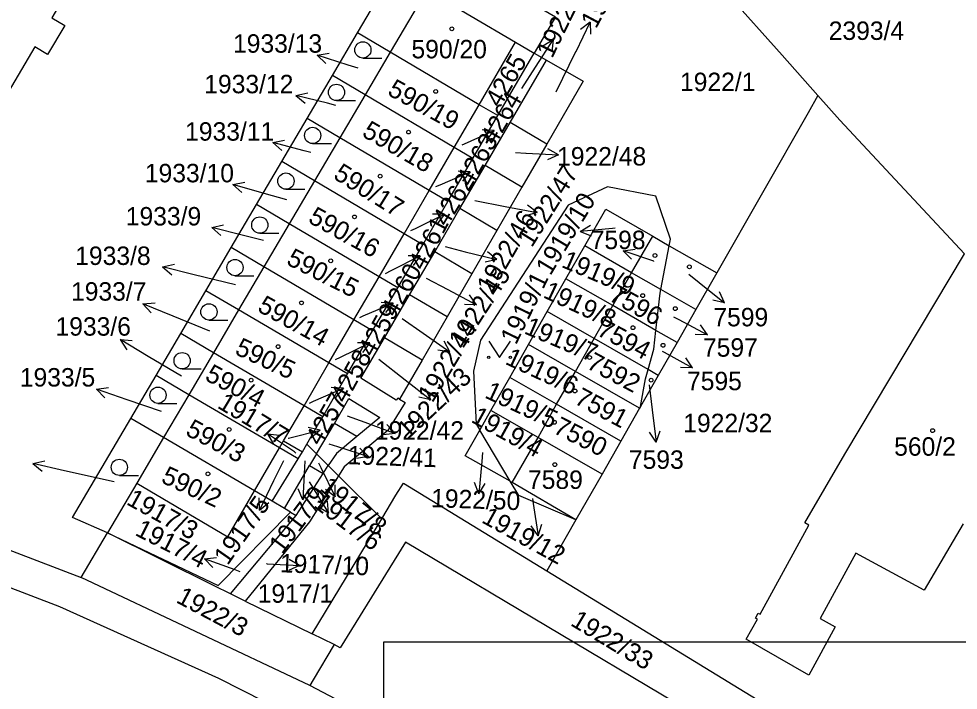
# Model space of a CAD drawing. Extents: x -667048 to -665920, y -1108425 to -1107247.
# Drawn here: x -666872 to -666785.4, y -1107347.8 to -1107285.9 of the extents above; entities that cross this region are included whole.
import ezdxf

# ---------------------------------------------------------------- set-up
doc = ezdxf.new("R2010")
doc.units = 0
for name, color, linetype in [('Default', 7, 'Continuous'), ('Hranice parcel', 7, 'Continuous'), ('Parcelní čísla', 7, 'Continuous'), ('Pop_ PČ_ popisy', 7, 'Continuous'), ('Vrstva 2', 7, 'Continuous'), ('Značky budov', 7, 'Continuous'), ('Značky kultur', 7, 'Continuous')]:
    doc.layers.add(name, color=color, linetype=linetype)

# ---------------------------------------------------------------- blocks, each defined once
blk = doc.blocks.new('3.041')
at = {"layer": 'Default'}
blk.add_line((8, 0), (1758, 0), dxfattribs=at)
blk.add_circle((8, 750), 750, dxfattribs=at)
blk = doc.blocks.new('4.021')
at = {"layer": 'Default'}
blk.add_circle((-7, 1), 175, dxfattribs=at)
blk = doc.blocks.new('3.141')
at = {"layer": 'Default'}
blk.add_lwpolyline([(-1000, 1500), (0, 0), (1000, 1500)], dxfattribs=at)
for centre in [(-1000, 0), (1000, 0)]:
    blk.add_circle(centre, 100, dxfattribs=at)
blk = doc.blocks.new('10291')
at = {"layer": 'Default'}
for p, q in [((0, 3001), (-500, 2001)), ((0, 1), (0, 3001)), ((0, 3001), (500, 2001))]:
    blk.add_line(p, q, dxfattribs=at)

msp = doc.modelspace()

# ---------------------------------------------------------------- linework, layer by layer
at = {"layer": 'Hranice parcel'}
for points in [[(-666858.24, -1107267.45), (-666869, -1107285.85), (-666867.8, -1107286.56), (-666869.39, -1107289.23), (-666870.57, -1107288.53), (-666873.32, -1107293.22)], [(-666825.77, -1107268.56), (-666817.61, -1107273.24), (-666820.44, -1107278.11), (-666824.3, -1107284.74), (-666822.57, -1107285.74), (-666824.52, -1107289.09)], [(-666840.81, -1107287.22), (-666837.43, -1107281.48)], [(-666834.41, -1107283.26), (-666837.79, -1107289.01)], [(-666834.41, -1107283.26), (-666826.25, -1107288.09)], [(-666806.68, -1107283.67), (-666801.66, -1107289.3), (-666798.36, -1107293)], [(-666843.12, -1107291.16), (-666840.81, -1107287.22)], [(-666837.79, -1107289.01), (-666840.81, -1107287.22)], [(-666829.6, -1107293.86), (-666826.25, -1107288.09)], [(-666826.25, -1107288.09), (-666824.52, -1107289.09)], [(-666837.79, -1107289.01), (-666840.1, -1107292.94)], [(-666829.6, -1107293.86), (-666837.79, -1107289.01)], [(-666827.87, -1107294.86), (-666824.52, -1107289.09)], [(-666824.52, -1107289.09), (-666823.38, -1107289.75)], [(-666826.75, -1107295.51), (-666823.38, -1107289.75)], [(-666823.38, -1107289.75), (-666820.01, -1107291.69), (-666823.36, -1107297.48)], [(-666845.45, -1107295.13), (-666843.12, -1107291.16)], [(-666840.1, -1107292.94), (-666843.12, -1107291.16)], [(-666840.1, -1107292.94), (-666842.43, -1107296.91)], [(-666831.89, -1107297.79), (-666840.1, -1107292.94)], [(-666798.36, -1107293), (-666799.27, -1107294.6), (-666807.7, -1107309.37)], [(-666798.36, -1107293), (-666796.34, -1107295.27), (-666784.84, -1107307.59)], [(-666831.89, -1107297.79), (-666829.6, -1107293.86)], [(-666827.87, -1107294.86), (-666829.6, -1107293.86)], [(-666847.79, -1107299.1), (-666845.45, -1107295.13)], [(-666842.43, -1107296.91), (-666845.45, -1107295.13)], [(-666830.17, -1107298.81), (-666827.87, -1107294.86)], [(-666829.06, -1107299.47), (-666826.75, -1107295.51)], [(-666823.36, -1107297.48), (-666826.75, -1107295.51)], [(-666842.43, -1107296.91), (-666844.77, -1107300.88)], [(-666834.2, -1107301.77), (-666842.43, -1107296.91)], [(-666834.2, -1107301.77), (-666831.89, -1107297.79)], [(-666830.17, -1107298.81), (-666831.89, -1107297.79)], [(-666823.36, -1107297.48), (-666825.66, -1107301.47)], [(-666832.48, -1107302.78), (-666830.17, -1107298.81)], [(-666850.12, -1107303.06), (-666847.79, -1107299.1)], [(-666844.77, -1107300.88), (-666847.79, -1107299.1)], [(-666831.38, -1107303.43), (-666829.06, -1107299.47)], [(-666825.66, -1107301.47), (-666829.06, -1107299.47)], [(-666844.77, -1107300.88), (-666847.11, -1107304.84)], [(-666836.52, -1107305.75), (-666844.77, -1107300.88)], [(-666812.07, -1107306.86), (-666811.95, -1107306.25), (-666813.3, -1107302.28), (-666817.78, -1107301.43), (-666821.39, -1107303.12), (-666829.47, -1107315.58), (-666830.13, -1107318.42), (-666829.87, -1107323.29), (-666829.53, -1107323.86)], [(-666825.66, -1107301.47), (-666827.96, -1107305.45)], [(-666836.52, -1107305.75), (-666834.2, -1107301.77)], [(-666832.48, -1107302.78), (-666834.2, -1107301.77)], [(-666852.46, -1107307.03), (-666850.12, -1107303.06)], [(-666847.11, -1107304.84), (-666850.12, -1107303.06)], [(-666834.8, -1107306.77), (-666832.48, -1107302.78)], [(-666833.7, -1107307.42), (-666831.38, -1107303.43)], [(-666827.96, -1107305.45), (-666831.38, -1107303.43)], [(-666819.87, -1107306.86), (-666817.93, -1107303.49), (-666813.6, -1107305.98)], [(-666847.11, -1107304.84), (-666849.44, -1107308.81)], [(-666838.83, -1107309.72), (-666847.11, -1107304.84)], [(-666838.83, -1107309.72), (-666836.52, -1107305.75)], [(-666834.8, -1107306.77), (-666836.52, -1107305.75)], [(-666827.96, -1107305.45), (-666830.27, -1107309.44)], [(-666815.54, -1107309.35), (-666813.6, -1107305.98)], [(-666813.6, -1107305.98), (-666812.07, -1107306.86)], [(-666837.11, -1107310.74), (-666834.8, -1107306.77)], [(-666821.61, -1107309.9), (-666819.87, -1107306.86)], [(-666815.54, -1107309.35), (-666819.87, -1107306.86)], [(-666812.85, -1107310.89), (-666812.07, -1107306.86)], [(-666812.07, -1107306.86), (-666807.7, -1107309.37)], [(-666854.79, -1107311.01), (-666852.46, -1107307.03)], [(-666849.44, -1107308.81), (-666852.46, -1107307.03)], [(-666836.02, -1107311.38), (-666833.7, -1107307.42)], [(-666830.27, -1107309.44), (-666833.7, -1107307.42)], [(-666799.56, -1107332.42), (-666795.89, -1107326.08), (-666784.84, -1107307.59)], [(-666849.44, -1107308.81), (-666851.78, -1107312.78)], [(-666841.14, -1107313.7), (-666849.44, -1107308.81)], [(-666830.27, -1107309.44), (-666832.56, -1107313.42)], [(-666817.27, -1107312.38), (-666815.54, -1107309.35)], [(-666812.85, -1107310.89), (-666815.54, -1107309.35)], [(-666807.7, -1107309.37), (-666809.62, -1107312.74)], [(-666841.14, -1107313.7), (-666838.83, -1107309.72)], [(-666837.11, -1107310.74), (-666838.83, -1107309.72)], [(-666823.32, -1107312.93), (-666821.61, -1107309.9)], [(-666817.27, -1107312.38), (-666821.61, -1107309.9)], [(-666857.11, -1107314.95), (-666854.79, -1107311.01)], [(-666851.78, -1107312.78), (-666854.79, -1107311.01)], [(-666839.42, -1107314.71), (-666837.11, -1107310.74)], [(-666813.3, -1107314.66), (-666812.91, -1107311.23), (-666812.85, -1107310.89)], [(-666809.62, -1107312.74), (-666812.85, -1107310.89)], [(-666838.33, -1107315.35), (-666836.02, -1107311.38)], [(-666832.56, -1107313.42), (-666836.02, -1107311.38)], [(-666851.78, -1107312.78), (-666854.09, -1107316.72)], [(-666843.45, -1107317.67), (-666851.78, -1107312.78)], [(-666825.05, -1107315.97), (-666823.32, -1107312.93)], [(-666818.99, -1107315.42), (-666823.32, -1107312.93)], [(-666818.99, -1107315.42), (-666817.27, -1107312.38)], [(-666813.3, -1107314.66), (-666817.27, -1107312.38)], [(-666809.62, -1107312.74), (-666811.35, -1107315.78)], [(-666936.4, -1107313.14), (-666921.72, -1107316.2), (-666866.28, -1107337.45)], [(-666843.45, -1107317.67), (-666841.14, -1107313.7)], [(-666839.42, -1107314.71), (-666841.14, -1107313.7)], [(-666832.56, -1107313.42), (-666834.86, -1107317.4)], [(-666814.01, -1107318.28), (-666813.49, -1107316.38), (-666813.3, -1107314.66)], [(-666811.35, -1107315.78), (-666813.3, -1107314.66)], [(-666859.39, -1107318.83), (-666857.11, -1107314.95)], [(-666854.09, -1107316.72), (-666857.11, -1107314.95)], [(-666841.73, -1107318.68), (-666839.42, -1107314.71)], [(-666836.95, -1107321.01), (-666837.11, -1107320.92), (-666837.24, -1107321.1), (-666840.5, -1107319.06), (-666838.33, -1107315.35)], [(-666834.86, -1107317.4), (-666838.33, -1107315.35)], [(-666820.71, -1107318.46), (-666818.99, -1107315.42)], [(-666814.01, -1107318.28), (-666818.99, -1107315.42)], [(-666826.78, -1107319.02), (-666825.05, -1107315.97)], [(-666820.71, -1107318.46), (-666825.05, -1107315.97)], [(-666811.35, -1107315.78), (-666813.08, -1107318.81)], [(-666854.09, -1107316.72), (-666856.37, -1107320.6)], [(-666845.74, -1107321.61), (-666854.09, -1107316.72)], [(-666845.74, -1107321.61), (-666843.45, -1107317.67)], [(-666841.73, -1107318.68), (-666843.45, -1107317.67)], [(-666834.86, -1107317.4), (-666836.95, -1107321.01)], [(-666861.71, -1107322.78), (-666859.39, -1107318.83)], [(-666856.37, -1107320.6), (-666859.39, -1107318.83)], [(-666844.02, -1107322.62), (-666841.73, -1107318.68)], [(-666822.46, -1107321.48), (-666820.71, -1107318.46)], [(-666814.81, -1107321.84), (-666820.71, -1107318.46)], [(-666814.71, -1107321.67), (-666814.25, -1107319.14), (-666814.01, -1107318.28)], [(-666813.08, -1107318.81), (-666814.71, -1107321.67)], [(-666813.08, -1107318.81), (-666814.01, -1107318.28)], [(-666828.51, -1107322.06), (-666826.78, -1107319.02)], [(-666822.46, -1107321.48), (-666826.78, -1107319.02)], [(-666856.37, -1107320.6), (-666858.69, -1107324.55)], [(-666848.01, -1107325.5), (-666856.37, -1107320.6)], [(-666868.25, -1107340.16), (-666917.47, -1107321.28)], [(-666847.63, -1107324.85), (-666845.74, -1107321.61)], [(-666844.02, -1107322.62), (-666845.74, -1107321.61)], [(-666842.95, -1107323.24), (-666841.6, -1107320.93), (-666838.77, -1107322.71), (-666840.87, -1107324.46)], [(-666836.95, -1107321.01), (-666836.42, -1107321.3), (-666838.01, -1107323.89), (-666842.04, -1107327.26), (-666842.56, -1107328.08)], [(-666824.17, -1107324.53), (-666822.46, -1107321.48)], [(-666816.54, -1107324.87), (-666822.46, -1107321.48)], [(-666829.53, -1107323.86), (-666828.51, -1107322.06)], [(-666824.17, -1107324.53), (-666828.51, -1107322.06)], [(-666814.81, -1107321.84), (-666816.54, -1107324.87)], [(-666814.71, -1107321.67), (-666814.81, -1107321.84)], [(-666863.86, -1107333.33), (-666867.1, -1107331.93), (-666861.71, -1107322.78)], [(-666858.69, -1107324.55), (-666861.71, -1107322.78)], [(-666845.5, -1107325.16), (-666844.49, -1107323.43), (-666844.02, -1107322.62)], [(-666844.6, -1107326.05), (-666842.95, -1107323.24)], [(-666840.87, -1107324.46), (-666842.95, -1107323.24)], [(-666826.73, -1107328.58), (-666830.88, -1107326.22), (-666829.53, -1107323.86)], [(-666826.73, -1107328.58), (-666829.53, -1107323.86)], [(-666858.69, -1107324.55), (-666861.17, -1107328.76)], [(-666850.31, -1107329.47), (-666858.69, -1107324.55)], [(-666848.01, -1107325.5), (-666847.63, -1107324.85)], [(-666847.63, -1107324.85), (-666845.9, -1107325.85)], [(-666840.87, -1107324.46), (-666842.74, -1107326.03), (-666843.52, -1107327.12)], [(-666826.54, -1107328.69), (-666824.17, -1107324.53)], [(-666818.27, -1107327.91), (-666824.17, -1107324.53)], [(-666816.54, -1107324.87), (-666818.27, -1107327.91)], [(-666850.31, -1107329.47), (-666848.01, -1107325.5)], [(-666846.3, -1107326.5), (-666848.01, -1107325.5)], [(-666846.3, -1107326.5), (-666845.9, -1107325.85)], [(-666845.9, -1107325.85), (-666845.5, -1107325.16)], [(-666844.6, -1107326.05), (-666845.5, -1107325.16)], [(-666848.69, -1107330.42), (-666846.3, -1107326.5)], [(-666844.6, -1107326.05), (-666845.23, -1107327.13)], [(-666843.52, -1107327.12), (-666844.6, -1107326.05)], [(-666847.55, -1107331.09), (-666845.23, -1107327.13)], [(-666845.23, -1107327.13), (-666843.99, -1107327.86)], [(-666843.99, -1107327.86), (-666843.52, -1107327.12)], [(-666843.52, -1107327.12), (-666842.56, -1107328.08)], [(-666846.48, -1107331.72), (-666843.99, -1107327.86)], [(-666842.56, -1107328.08), (-666845.23, -1107332.31)], [(-666838.58, -1107332.03), (-666842.56, -1107328.08)], [(-666818.27, -1107327.91), (-666820.68, -1107332.13)], [(-666861.17, -1107328.76), (-666863.86, -1107333.33)], [(-666861.17, -1107328.76), (-666852.78, -1107333.71), (-666850.31, -1107329.47)], [(-666838.58, -1107332.03), (-666837.27, -1107329.87), (-666836.58, -1107328.74), (-666823.36, -1107336.83)], [(-666826.73, -1107328.58), (-666826.54, -1107328.69)], [(-666820.68, -1107332.13), (-666825.95, -1107329.9), (-666826.73, -1107328.58)], [(-666820.68, -1107332.13), (-666826.54, -1107328.69)], [(-666848.69, -1107330.42), (-666850.31, -1107329.47)], [(-666847.55, -1107331.09), (-666848.69, -1107330.42)], [(-666847, -1107331.41), (-666847.55, -1107331.09)], [(-666863.86, -1107333.33), (-666853.67, -1107338.18), (-666847, -1107331.41)], [(-666852.53, -1107338.96), (-666846.48, -1107331.72)], [(-666847, -1107331.41), (-666846.48, -1107331.72)], [(-666845.23, -1107332.31), (-666851.17, -1107339.62)], [(-666845.01, -1107342.64), (-666838.58, -1107332.03)], [(-666820.68, -1107332.13), (-666823.36, -1107336.83)], [(-666784.96, -1107332.49), (-666788.58, -1107338.62), (-666794.87, -1107335.19), (-666798.17, -1107341.22), (-666796.76, -1107341.99), (-666799.2, -1107346.46), (-666804.99, -1107343.15), (-666803.95, -1107341.29), (-666804.12, -1107341.19), (-666803.87, -1107340.74), (-666803.7, -1107340.83)], [(-666803.7, -1107340.83), (-666799.21, -1107332.61), (-666799.56, -1107332.42)], [(-666866.28, -1107337.45), (-666863.86, -1107333.33)], [(-666852.53, -1107338.96), (-666854.04, -1107338.22), (-666863.86, -1107333.33)], [(-666802.13, -1107369.26), (-666797.19, -1107361.18), (-666801.4, -1107358.68), (-666799.78, -1107355.98), (-666835.11, -1107334.96), (-666836.4, -1107334.2), (-666842.42, -1107343.92), (-666842.98, -1107343.64)], [(-666823.36, -1107336.83), (-666789.95, -1107357.28), (-666799.44, -1107371.3)], [(-666845.22, -1107347.42), (-666866.28, -1107337.45)], [(-666851.17, -1107339.62), (-666852.53, -1107338.96)], [(-666851.17, -1107339.62), (-666845.01, -1107342.64)], [(-666683.99, -1107517.16), (-666734.88, -1107443.83), (-666739.56, -1107437.74), (-666744.57, -1107431.79), (-666763.51, -1107413.08), (-666776.63, -1107400.64), (-666782.75, -1107395.17), (-666793.33, -1107386.18), (-666809.9, -1107373.11), (-666816.72, -1107368.16), (-666833.93, -1107357.1), (-666840.83, -1107353.24), (-666853.59, -1107346.76), (-666868.25, -1107340.16)], [(-666842.98, -1107343.64), (-666845.01, -1107342.64)], [(-666842.98, -1107343.64), (-666844.91, -1107346.9), (-666845.22, -1107347.42)], [(-666811.55, -1107367.48), (-666833.4, -1107353.62), (-666845.22, -1107347.42)]]:
    msp.add_lwpolyline(points, dxfattribs=at)
at = {"layer": 'Pop_ PČ_ popisy'}
for points in [[(-666822.49, -1107292.68), (-666820.67, -1107288.94)], [(-666840.75, -1107290.5), (-666841.69, -1107290.2)], [(-666825.67, -1107292.37), (-666824.41, -1107290.4)], [(-666842.8, -1107293.92), (-666843.58, -1107293.72)], [(-666845.12, -1107298.27), (-666845.73, -1107298.12)], [(-666831.18, -1107297.55), (-666830.96, -1107297.45)], [(-666826.24, -1107298.27), (-666825.28, -1107298.32)], [(-666833.6, -1107301.41), (-666833.18, -1107301.23)], [(-666847.32, -1107302.62), (-666849.43, -1107302.03)], [(-666830.01, -1107302.68), (-666827.21, -1107303.23)], [(-666849.49, -1107306.38), (-666851.34, -1107305.91)], [(-666835.89, -1107305.46), (-666835.48, -1107305.26)], [(-666817.05, -1107305.25), (-666817.31, -1107305.27)], [(-666832.72, -1107306.94), (-666830.88, -1107307.41)], [(-666813.49, -1107308.3), (-666813.49, -1107308.29)], [(-666838.22, -1107309.41), (-666837.7, -1107309.14)], [(-666810.26, -1107309.48), (-666809.3, -1107310.24)], [(-666852.07, -1107310.47), (-666855.87, -1107309.53)], [(-666834.47, -1107309.85), (-666832.49, -1107310.89)], [(-666854.43, -1107314.73), (-666857.81, -1107313.34)], [(-666840.6, -1107313.46), (-666840.28, -1107313.33)], [(-666836.69, -1107313.56), (-666834.75, -1107314.92)], [(-666811.67, -1107313.4), (-666811.2, -1107313.65)], [(-666857.03, -1107318.9), (-666860.12, -1107317.06)], [(-666842.85, -1107317.36), (-666842.38, -1107317.13)], [(-666812.72, -1107316.58), (-666812.55, -1107316.67)], [(-666838.84, -1107317.33), (-666836.43, -1107319.21)], [(-666813.92, -1107319.67), (-666813.64, -1107322)], [(-666858.88, -1107322.15), (-666862.05, -1107321.06)], [(-666845.24, -1107321.36), (-666844.86, -1107321.2)], [(-666841.78, -1107322.54), (-666840.15, -1107323.13)], [(-666847.22, -1107324.61), (-666847.18, -1107324.6)], [(-666846.49, -1107325.97), (-666846.63, -1107325.87)], [(-666843.47, -1107325.11), (-666842.65, -1107325.38)], [(-666829.29, -1107325.92), (-666829.36, -1107326.74)], [(-666847.64, -1107326.69), (-666848.55, -1107328.53)], [(-666845.66, -1107326.69), (-666845.69, -1107327.3)], [(-666863.25, -1107328.63), (-666867.82, -1107327.62)], [(-666844.41, -1107326.88), (-666844.2, -1107327.31)], [(-666845.28, -1107328.64), (-666845.07, -1107328.97)], [(-666824.69, -1107330.18), (-666824.62, -1107330.63)], [(-666849.15, -1107336.19), (-666849.22, -1107336.19)], [(-666851.64, -1107336.92), (-666852.1, -1107336.75)]]:
    msp.add_lwpolyline(points, dxfattribs=at)
at = {"layer": 'Vrstva 2'}
msp.add_lwpolyline([(-666838.388, -1107343.373), (-666244.388, -1107343.373), (-666244.388, -1108183.373), (-666838.388, -1108183.373)], close=True, dxfattribs=at)

# ---------------------------------------------------------------- block references
at = {"layer": 'Pop_ PČ_ popisy'}
for p, xscale, yscale, rotation in [((-666820.67, -1107288.94), 0.001, 0.001, -25.999999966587), ((-666824.41, -1107290.4), 0.001, 0.0010000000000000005, -32.99999998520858), ((-666841.69, -1107290.2), 0.0010000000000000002, 0.0010000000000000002, 71.99999994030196), ((-666843.58, -1107293.72), 0.0010000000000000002, 0.0010000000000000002, 76.00000000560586), ((-666830.96, -1107297.45), 0.0010000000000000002, 0.0010000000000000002, -65.99999994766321), ((-666845.73, -1107298.12), 0.001, 0.0010000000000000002, 74.99999992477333), ((-666825.28, -1107298.32), 0.001, 0.0010000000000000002, -92.99999999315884), ((-666833.18, -1107301.23), 0.0010000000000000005, 0.001, -67.00000000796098), ((-666849.43, -1107302.03), 0.001, 0.0010000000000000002, 74.00000000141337), ((-666827.21, -1107303.23), 0.001, 0.001, -100.99999997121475), ((-666835.48, -1107305.26), 0.0010000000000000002, 0.0010000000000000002, -63.99999997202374), ((-666851.34, -1107305.91), 0.0010000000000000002, 0.0010000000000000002, 76.00000000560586), ((-666817.31, -1107305.27), 0.0010000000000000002, 0.001, 95.00000005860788), ((-666813.49, -1107308.29), 0.001, 0.001, 71.00000001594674), ((-666837.7, -1107309.14), 0.0010000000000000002, 0.0010000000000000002, -62.99999993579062), ((-666830.88, -1107307.41), 0.0010000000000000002, 0.0010000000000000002, -104.00000002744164), ((-666855.87, -1107309.53), 0.0010000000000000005, 0.0010000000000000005, 75.99999997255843), ((-666809.3, -1107310.24), 0.0010000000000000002, 0.001, -128.99999997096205), ((-666832.49, -1107310.89), 0.001, 0.0010000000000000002, -118.00000001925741), ((-666857.81, -1107313.34), 0.0010000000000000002, 0.0010000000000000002, 67.99999992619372), ((-666840.28, -1107313.33), 0.0010000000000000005, 0.001, -67.00000000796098), ((-666811.2, -1107313.65), 0.001, 0.0010000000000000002, -118.00000001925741), ((-666834.75, -1107314.92), 0.001, 0.001, -125.00000003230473), ((-666860.12, -1107317.06), 0.0010000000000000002, 0.0010000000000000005, 58.999999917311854), ((-666842.38, -1107317.13), 0.0010000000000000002, 0.0010000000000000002, -63.99999991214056), ((-666812.55, -1107316.67), 0.0010000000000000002, 0.0010000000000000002, -119.00000010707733), ((-666836.43, -1107319.21), 0.0010000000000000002, 0.0010000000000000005, -127.99999998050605), ((-666862.05, -1107321.06), 0.001, 0.001, 71.00000001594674), ((-666844.86, -1107321.2), 0.0010000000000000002, 0.0010000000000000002, -65.99999994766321), ((-666813.64, -1107322), 0.0010000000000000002, 0.0010000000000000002, -173.00000006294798), ((-666840.15, -1107323.13), 0.0009999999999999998, 0.0010000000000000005, -110.00000003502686), ((-666846.63, -1107325.87), 0.0010000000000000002, 0.0010000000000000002, 55.999999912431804), ((-666847.18, -1107324.6), 0.0010000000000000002, 0.0010000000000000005, -76.00000007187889), ((-666842.65, -1107325.38), 0.001, 0.0010000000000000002, -108.00000003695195), ((-666867.82, -1107327.62), 0.0010000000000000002, 0.0010000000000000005, 76.99999992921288), ((-666829.36, -1107326.74), 0.001, 0.001, 175.00000000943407), ((-666845.69, -1107327.3), 0.001, 0.0010000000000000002, 177.0000000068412), ((-666844.2, -1107327.31), 0.0009999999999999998, 0.001, -153.99999991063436), ((-666848.55, -1107328.53), 0.0010000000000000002, 0.0010000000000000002, 154.00000006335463), ((-666845.07, -1107328.97), 0.001, 0.0009999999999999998, -147.99999998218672), ((-666824.62, -1107330.63), 0.0010000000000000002, 0.0010000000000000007, -171.0000000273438), ((-666852.1, -1107336.75), 0.0010000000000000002, 0.0010000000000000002, 69.99999996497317), ((-666849.15, -1107336.19), 0.001, 0.0010000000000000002, -92.99999999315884)]:
    msp.add_blockref('10291', p, dxfattribs=dict(at, xscale=xscale, yscale=yscale, rotation=rotation))
at = {"layer": 'Značky budov', "xscale": 0.0010000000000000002, "yscale": 0.0010000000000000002}
for p in [(-666832.11, -1107286.86), (-666833.6, -1107292.63), (-666836.1, -1107296.38), (-666838.72, -1107300.45), (-666841.08, -1107304.2), (-666813.38, -1107307.76), (-666843.28, -1107308.25), (-666810.21, -1107308.81), (-666845.97, -1107312.13), (-666814.51, -1107311.46), (-666811.51, -1107312.66), (-666815.41, -1107314.42), (-666848.13, -1107316.16), (-666812.64, -1107316.04), (-666819.41, -1107317.17), (-666850.62, -1107319.25), (-666813.74, -1107319.25), (-666820.76, -1107320.25), (-666822.66, -1107323.14), (-666852.64, -1107323.8), (-666787.78, -1107323.91), (-666822.61, -1107327.04), (-666854.6, -1107327.89)]:
    msp.add_blockref('4.021', p, dxfattribs=at)
at = {"layer": 'Značky kultur', "xscale": 0.0010000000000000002, "yscale": 0.0010000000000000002}
for name, p in [('3.041', (-666840.33, -1107289.55)), ('3.041', (-666842.76, -1107293.47)), ('3.041', (-666844.96, -1107297.44)), ('3.041', (-666847.42, -1107301.65)), ('3.041', (-666849.83, -1107305.7)), ('3.041', (-666852.12, -1107309.62)), ('3.041', (-666854.52, -1107313.71)), ('3.141', (-666827.72, -1107317.15)), ('3.041', (-666856.99, -1107318.21)), ('3.041', (-666859.22, -1107321.39)), ('3.041', (-666862.78, -1107328.04))]:
    msp.add_blockref(name, p, dxfattribs=at)

# ---------------------------------------------------------------- texts
at = {"layer": 'Parcelní čísla'}
for s, rotation, p in [('1922/49', 62, (-666818.82, -1107286.919)), ('1922/51', 64, (-666822.874, -1107289.655)), ('4265', 60, (-666827.673, -1107294.207)), ('590/19', 331, (-666838.15, -1107292.89)), ('4264', 60, (-666828.123, -1107297.677)), ('590/18', 330, (-666840.5, -1107296.71)), ('4263', 60, (-666830.333, -1107301.517)), ('590/17', 328, (-666843.14, -1107300.6)), ('1922/47', 58, (-666824.742, -1107307.086)), ('4262', 59, (-666832.554, -1107305.193)), ('1919/10', 59, (-666823.031, -1107309.683)), ('590/16', 331, (-666845.464, -1107304.656)), ('1922/46', 60, (-666828.452, -1107311.35)), ('4261', 62, (-666834.722, -1107309.228)), ('590/15', 333, (-666847.47, -1107308.53)), ('1919/9', 337, (-666822.101, -1107308.795)), ('4260', 61, (-666837.273, -1107313.54)), ('1922/45', 57, (-666831.101, -1107316.412)), ('1919/1', 64, (-666826.199, -1107316.063)), ('1919/8', 335, (-666823.789, -1107311.588)), ('7596', 331, (-666817.745, -1107311.839)), ('590/14', 331, (-666850.14, -1107312.84)), ('4259', 61, (-666839.371, -1107317.205)), ('1922/44', 59, (-666833.903, -1107321.409)), ('1919/7', 337, (-666825.541, -1107314.915)), ('7594', 332, (-666818.848, -1107315.05)), ('590/5', 335, (-666852.22, -1107316.815)), ('4258', 61, (-666841.911, -1107321.475)), ('1919/6', 335, (-666827.289, -1107317.728)), ('7592', 332, (-666819.798, -1107318.1)), ('590/4', 332, (-666854.98, -1107319.194)), ('1922/43', 43, (-666836.182, -1107324.771)), ('1919/5', 335, (-666829.179, -1107320.828)), ('1917/7', 329, (-666853.828, -1107321.748)), ('4257', 60, (-666844.242, -1107325.402)), ('7591', 332, (-666820.924, -1107321.36)), ('1919/4', 331, (-666830.432, -1107323.069)), ('590/3', 332, (-666856.77, -1107324.264)), ('7590', 333, (-666822.87, -1107324.062)), ('1922/41', 358, (-666841.738, -1107326.996)), ('590/2', 335, (-666859.02, -1107328.645)), ('1917/8', 321, (-666844.384, -1107329.339)), ('1917/9', 53, (-666847.76, -1107335.373)), ('1922/50', 358, (-666834.052, -1107330.957)), ('1917/3', 331, (-666862.212, -1107330.659)), ('1917/5', 55, (-666852.787, -1107336.399)), ('1917/6', 323, (-666844.953, -1107330.89)), ('1919/12', 331, (-666829.466, -1107332.325)), ('1917/4', 333, (-666861.423, -1107333.503)), ('1917/10', 358, (-666847.995, -1107336.965)), ('1922/3', 332, (-666857.63, -1107339.7)), ('1922/33', 329, (-666821.27, -1107341.81))]:
    msp.add_text(s, height=1.7, rotation=rotation, dxfattribs=at).set_placement(p)
for s, p in [('2393/4', (-666797.37, -1107287.88)), ('1933/13', (-666852.294, -1107289.06)), ('590/20', (-666835.84, -1107289.58)), ('1933/12', (-666854.944, -1107292.8)), ('1922/1', (-666811.083, -1107292.6)), ('1933/11', (-666856.71, -1107297.17)), ('1922/48', (-666822.415, -1107299.46)), ('1933/10', (-666860.424, -1107301.01)), ('1933/9', (-666862.18, -1107304.99)), ('7598', (-666819.314, -1107307.17)), ('1933/8', (-666866.84, -1107308.63)), ('1933/7', (-666867.23, -1107311.92)), ('7599', (-666808.004, -1107314.29)), ('1933/6', (-666868.66, -1107315.15)), ('7597', (-666808.964, -1107317.09)), ('1933/5', (-666871.95, -1107319.84)), ('7595', (-666810.434, -1107320.18)), ('1922/32', (-666810.78, -1107324.05)), ('1922/42', (-666839.215, -1107324.74)), ('560/2', (-666791.335, -1107326.22)), ('7593', (-666815.794, -1107327.43)), ('7589', (-666825.094, -1107329.28)), ('1917/1', (-666850.019, -1107339.78))]:
    msp.add_text(s, height=1.7, dxfattribs=at).set_placement(p)

doc.saveas('drawing.dxf')
